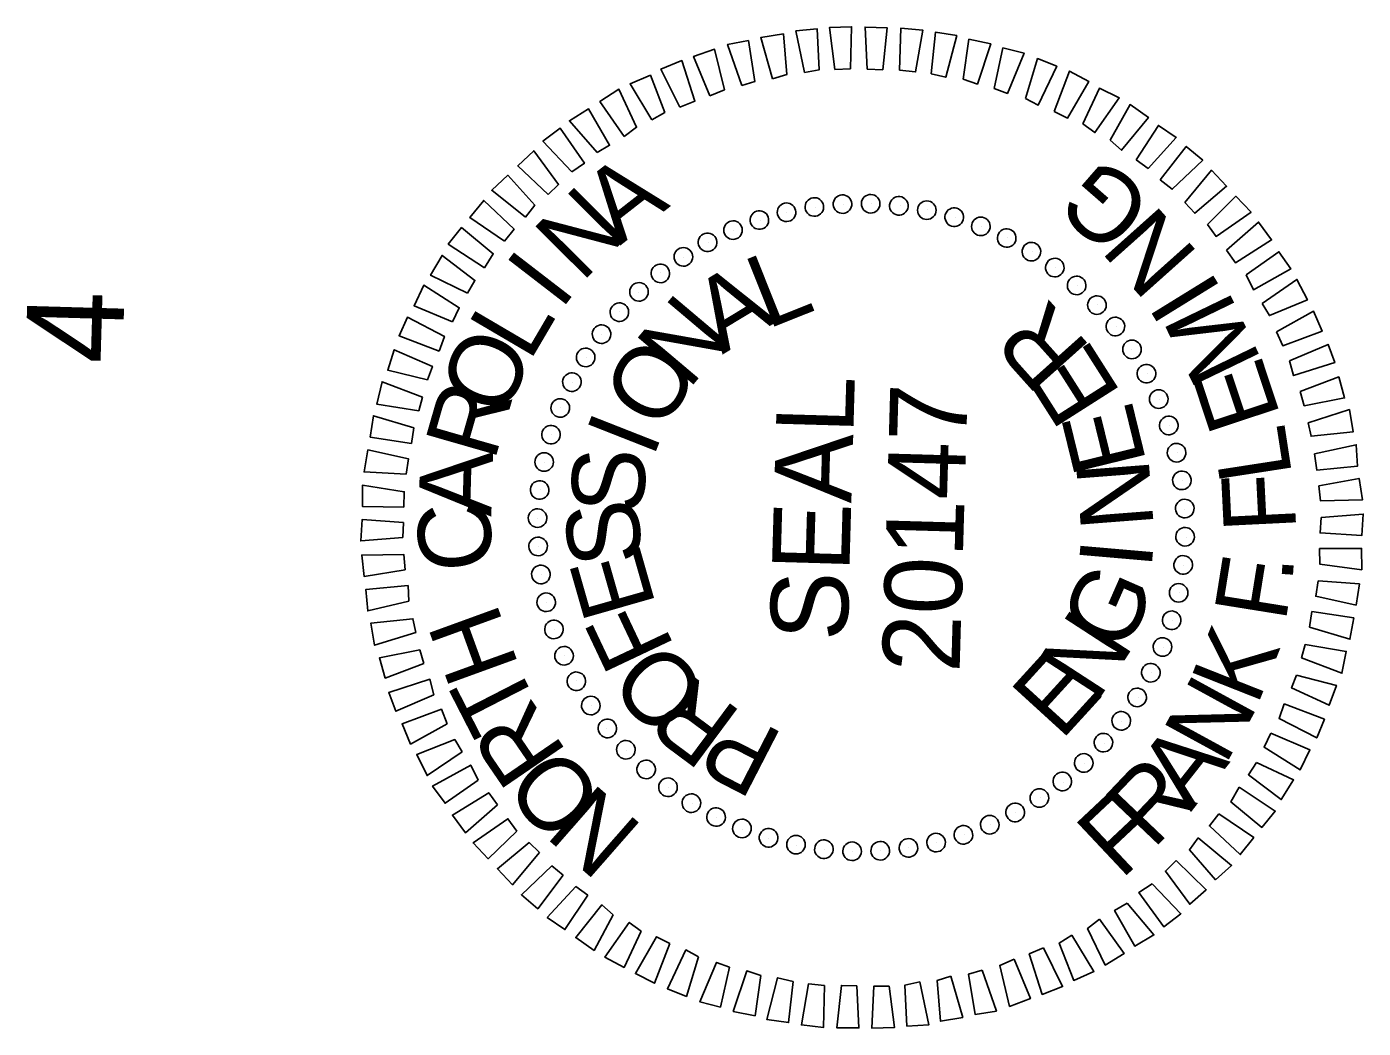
# Model space of a CAD drawing. Extents: x 2098230 to 2099272, y 990384 to 991889.
# Drawn here: x 2098261.7 to 2098365.1, y 991811.7 to 991889.2 of the extents above; entities that cross this region are included whole.
import ezdxf

# ---------------------------------------------------------------- set-up
doc = ezdxf.new("R2010")
doc.units = 0
doc.layers.add('Sheet Data Field CELL', color=7, linetype='Continuous')
doc.layers.add('Sheet PE Seal Cell', color=7, linetype='Continuous')

msp = doc.modelspace()

# ---------------------------------------------------------------- linework, layer by layer
at = {"layer": 'Sheet PE Seal Cell'}
for p, q in [((2098327.07, 991875.54), (2098327.07, 991875.54)), ((2098320.49, 991874.83), (2098320.49, 991874.83)), ((2098322.71, 991875.22), (2098322.71, 991875.22)), ((2098324.86, 991875.46), (2098324.86, 991875.46)), ((2098329.26, 991875.38), (2098329.26, 991875.38)), ((2098331.35, 991875.02), (2098331.35, 991875.02)), ((2098316.4, 991873.45), (2098316.4, 991873.45)), ((2098318.43, 991874.24), (2098318.43, 991874.24)), ((2098333.54, 991874.46), (2098333.54, 991874.46)), ((2098335.57, 991873.75), (2098335.57, 991873.75)), ((2098314.42, 991872.51), (2098314.42, 991872.51)), ((2098337.55, 991872.89), (2098337.55, 991872.89)), ((2098339.47, 991871.83), (2098339.47, 991871.83)), ((2098312.54, 991871.36), (2098312.54, 991871.36)), ((2098341.28, 991870.58), (2098341.28, 991870.58)), ((2098310.76, 991870.16), (2098310.76, 991870.16)), ((2098309.06, 991868.66), (2098309.06, 991868.66)), ((2098342.99, 991869.18), (2098342.99, 991869.18)), ((2098344.55, 991867.69), (2098344.55, 991867.69)), ((2098307.57, 991867.15), (2098307.57, 991867.15)), ((2098306.17, 991865.39), (2098306.17, 991865.39)), ((2098346, 991865.99), (2098346, 991865.99)), ((2098347.2, 991864.21), (2098347.2, 991864.21)), ((2098304.97, 991863.62), (2098304.97, 991863.62)), ((2098348.4, 991862.37), (2098348.4, 991862.37)), ((2098303.91, 991861.7), (2098303.91, 991861.7)), ((2098349.34, 991860.34), (2098349.34, 991860.34)), ((2098303, 991859.73), (2098303, 991859.73)), ((2098350.13, 991858.32), (2098350.13, 991858.32)), ((2098302.29, 991857.65), (2098302.29, 991857.65)), ((2098350.72, 991856.25), (2098350.72, 991856.25)), ((2098301.78, 991855.51), (2098301.78, 991855.51)), ((2098351.11, 991854.09), (2098351.11, 991854.09)), ((2098301.42, 991853.37), (2098301.42, 991853.37)), ((2098351.3, 991851.88), (2098351.3, 991851.88)), ((2098301.21, 991851.18), (2098301.21, 991851.18)), ((2098351.38, 991849.68), (2098351.38, 991849.68)), ((2098301.29, 991848.97), (2098301.29, 991848.97)), ((2098301.53, 991846.82), (2098301.53, 991846.82)), ((2098351.22, 991847.54), (2098351.22, 991847.54)), ((2098301.92, 991844.65), (2098301.92, 991844.65)), ((2098350.86, 991845.39), (2098350.86, 991845.39)), ((2098302.51, 991842.54), (2098302.51, 991842.54)), ((2098350.35, 991843.26), (2098350.35, 991843.26)), ((2098303.3, 991840.56), (2098303.3, 991840.56)), ((2098349.64, 991841.18), (2098349.64, 991841.18)), ((2098304.24, 991838.58), (2098304.24, 991838.58)), ((2098348.73, 991839.2), (2098348.73, 991839.2)), ((2098347.67, 991837.28), (2098347.67, 991837.28)), ((2098305.39, 991836.7), (2098305.39, 991836.7)), ((2098346.42, 991835.47), (2098346.42, 991835.47)), ((2098306.59, 991834.87), (2098306.59, 991834.87)), ((2098308.09, 991833.22), (2098308.09, 991833.22)), ((2098345.07, 991833.76), (2098345.07, 991833.76)), ((2098343.53, 991832.2), (2098343.53, 991832.2)), ((2098309.6, 991831.68), (2098309.6, 991831.68)), ((2098311.36, 991830.33), (2098311.36, 991830.33)), ((2098341.88, 991830.75), (2098341.88, 991830.75)), ((2098313.17, 991829.07), (2098313.17, 991829.07)), ((2098340.1, 991829.55), (2098340.1, 991829.55)), ((2098315.09, 991828.02), (2098315.09, 991828.02)), ((2098338.21, 991828.4), (2098338.21, 991828.4)), ((2098317.07, 991827.11), (2098317.07, 991827.11)), ((2098336.24, 991827.46), (2098336.24, 991827.46)), ((2098319.1, 991826.4), (2098319.1, 991826.4)), ((2098321.24, 991825.89), (2098321.24, 991825.89)), ((2098332.1, 991826.08), (2098332.1, 991826.08)), ((2098334.21, 991826.67), (2098334.21, 991826.67)), ((2098323.38, 991825.53), (2098323.38, 991825.53)), ((2098325.57, 991825.36), (2098325.57, 991825.36)), ((2098327.78, 991825.45), (2098327.78, 991825.45)), ((2098329.93, 991825.69), (2098329.93, 991825.69))]:
    msp.add_line(p, q, dxfattribs=at)
for points in [[(2098321.86, 991885.65), (2098321.2, 991888.87), (2098322.85, 991889.02), (2098323.01, 991885.86)], [(2098324.21, 991885.88), (2098323.81, 991889.14), (2098325.51, 991889.19), (2098325.42, 991885.94)], [(2098326.72, 991885.91), (2098326.56, 991889.16), (2098328.26, 991889.11), (2098327.92, 991885.87)], [(2098329.22, 991885.83), (2098329.31, 991889.08), (2098331.01, 991888.93), (2098330.46, 991885.7)], [(2098317.03, 991884.64), (2098315.92, 991887.82), (2098317.53, 991888.12), (2098318.04, 991884.96)], [(2098319.39, 991885.17), (2098318.48, 991888.35), (2098320.24, 991888.64), (2098320.5, 991885.49)], [(2098331.66, 991885.56), (2098332, 991888.76), (2098333.64, 991888.51), (2098332.8, 991885.28)], [(2098334.15, 991885.14), (2098334.59, 991888.23), (2098336.28, 991887.88), (2098335.24, 991884.76)], [(2098314.55, 991883.86), (2098313.29, 991886.89), (2098314.91, 991887.45), (2098315.67, 991884.32)], [(2098336.53, 991884.42), (2098337.22, 991887.56), (2098338.86, 991887.16), (2098337.57, 991884.04)], [(2098312.23, 991882.97), (2098310.76, 991885.92), (2098312.38, 991886.57), (2098313.39, 991883.44)], [(2098338.96, 991883.65), (2098339.9, 991886.73), (2098341.38, 991886.13), (2098339.94, 991883.12)], [(2098310.05, 991881.99), (2098308.38, 991884.78), (2098309.95, 991885.44), (2098311.06, 991882.56)], [(2098341.18, 991882.64), (2098342.37, 991885.76), (2098343.85, 991884.96), (2098342.21, 991882.11)], [(2098307.91, 991880.7), (2098306.04, 991883.4), (2098307.51, 991884.36), (2098308.88, 991881.42)], [(2098343.4, 991881.67), (2098344.68, 991884.44), (2098346.21, 991883.69), (2098344.33, 991881)], [(2098305.82, 991879.46), (2098303.69, 991881.92), (2098305.17, 991882.83), (2098306.79, 991880.03)], [(2098345.52, 991880.41), (2098347.05, 991883.17), (2098348.47, 991882.18), (2098346.39, 991879.64)], [(2098303.88, 991877.96), (2098301.64, 991880.33), (2098302.97, 991881.34), (2098304.85, 991878.63)], [(2098347.52, 991878.9), (2098349.25, 991881.56), (2098350.62, 991880.62), (2098348.45, 991878.23)], [(2098349.38, 991877.35), (2098351.4, 991879.94), (2098352.67, 991878.86), (2098350.31, 991876.62)], [(2098302.03, 991876.21), (2098299.69, 991878.43), (2098300.92, 991879.6), (2098302.85, 991876.99)], [(2098300.28, 991874.46), (2098297.68, 991876.54), (2098298.92, 991877.7), (2098301, 991875.39)], [(2098351.28, 991875.6), (2098353.35, 991878.09), (2098354.52, 991876.85), (2098352.06, 991874.77)], [(2098298.67, 991872.61), (2098295.97, 991874.44), (2098297.06, 991875.76), (2098299.4, 991873.54)], [(2098353.03, 991873.89), (2098355.24, 991876.08), (2098356.41, 991874.85), (2098353.7, 991872.97)], [(2098297.11, 991870.55), (2098294.31, 991872.38), (2098295.35, 991873.66), (2098297.79, 991871.63)], [(2098354.52, 991871.9), (2098356.99, 991874.08), (2098358, 991872.7), (2098355.2, 991870.93)], [(2098295.8, 991868.59), (2098292.94, 991869.97), (2098293.84, 991871.5), (2098296.38, 991869.57)], [(2098356.02, 991870.01), (2098358.57, 991871.78), (2098359.48, 991870.46), (2098356.59, 991868.84)], [(2098357.26, 991867.77), (2098359.96, 991869.64), (2098360.77, 991868.07), (2098357.83, 991866.85)], [(2098294.64, 991866.37), (2098291.67, 991867.61), (2098292.42, 991869.19), (2098295.17, 991867.46)], [(2098293.62, 991864.1), (2098290.51, 991865.29), (2098291.15, 991866.72), (2098294.01, 991865.24)], [(2098358.39, 991865.59), (2098361.24, 991867.2), (2098361.9, 991865.64), (2098358.86, 991864.52)], [(2098292.71, 991861.88), (2098289.63, 991862.62), (2098290.13, 991864.2), (2098293.09, 991862.92)], [(2098359.38, 991863.36), (2098362.37, 991864.62), (2098362.88, 991863.21), (2098359.7, 991862.2)], [(2098360.21, 991860.98), (2098363.2, 991862.1), (2098363.65, 991860.48), (2098360.53, 991859.87)], [(2098292.04, 991859.49), (2098288.8, 991859.99), (2098289.2, 991861.73), (2098292.32, 991860.54)], [(2098291.47, 991856.96), (2098288.28, 991857.45), (2098288.53, 991859.1), (2098291.65, 991858.16)], [(2098360.84, 991858.56), (2098364.02, 991859.57), (2098364.32, 991857.86), (2098361.06, 991857.51)], [(2098291.05, 991854.57), (2098287.8, 991854.76), (2098288.1, 991856.46), (2098291.23, 991855.77)], [(2098361.32, 991856.15), (2098364.55, 991856.86), (2098364.65, 991855.2), (2098361.49, 991854.89)], [(2098361.65, 991853.69), (2098364.77, 991854.25), (2098365.02, 991852.59), (2098361.77, 991852.53)], [(2098290.88, 991852.03), (2098287.68, 991852.07), (2098287.67, 991853.72), (2098290.91, 991853.22)], [(2098290.81, 991849.68), (2098287.55, 991849.42), (2098287.65, 991851.07), (2098290.84, 991850.83)], [(2098361.83, 991851.23), (2098365.09, 991851.49), (2098364.99, 991849.84), (2098361.75, 991850.03)], [(2098361.71, 991848.83), (2098364.96, 991848.84), (2098364.97, 991847.19), (2098361.73, 991847.63)], [(2098290.99, 991847.17), (2098287.82, 991846.66), (2098287.62, 991848.32), (2098290.87, 991848.37)], [(2098291.27, 991844.76), (2098288.09, 991844), (2098287.94, 991845.66), (2098291.2, 991845.96)], [(2098361.59, 991846.34), (2098364.79, 991846.09), (2098364.54, 991844.45), (2098361.41, 991845.14)], [(2098361.12, 991843.95), (2098364.36, 991843.46), (2098364.06, 991841.81), (2098360.94, 991842.75)], [(2098291.8, 991842.34), (2098288.62, 991841.34), (2098288.32, 991843.05), (2098291.58, 991843.4)], [(2098360.6, 991841.41), (2098363.78, 991840.87), (2098363.44, 991839.18), (2098360.32, 991840.37)], [(2098292.43, 991839.93), (2098289.44, 991838.81), (2098288.99, 991840.37), (2098292.11, 991840.99)], [(2098293.21, 991837.5), (2098290.27, 991836.24), (2098289.71, 991837.7), (2098292.89, 991838.71)], [(2098359.93, 991839.03), (2098363.01, 991838.24), (2098362.46, 991836.71), (2098359.55, 991838.04)], [(2098294.24, 991835.27), (2098291.4, 991833.7), (2098290.74, 991835.27), (2098293.78, 991836.39)], [(2098358.97, 991836.81), (2098362.08, 991835.62), (2098361.49, 991834.18), (2098358.58, 991835.67)], [(2098357.95, 991834.54), (2098360.96, 991833.25), (2098360.22, 991831.72), (2098357.42, 991833.45)], [(2098295.38, 991833.09), (2098292.68, 991831.26), (2098291.87, 991832.89), (2098294.81, 991834.05)], [(2098356.83, 991832.27), (2098359.7, 991830.93), (2098358.75, 991829.41), (2098356.21, 991831.33)], [(2098296.62, 991830.9), (2098294.07, 991829.12), (2098293.1, 991830.45), (2098296.05, 991832.07)], [(2098355.48, 991830.36), (2098358.28, 991828.52), (2098357.24, 991827.25), (2098354.85, 991829.22)], [(2098298.12, 991829.01), (2098295.65, 991826.83), (2098294.64, 991828.21), (2098297.44, 991829.93)], [(2098353.92, 991828.3), (2098356.62, 991826.47), (2098355.58, 991825.15), (2098353.19, 991827.37)], [(2098299.61, 991826.96), (2098297.39, 991824.83), (2098296.23, 991826.06), (2098298.93, 991827.93)], [(2098301.36, 991825.31), (2098299.29, 991822.82), (2098298.12, 991824.05), (2098300.58, 991826.08)], [(2098352.31, 991826.45), (2098354.9, 991824.32), (2098353.67, 991823.2), (2098351.64, 991825.51)], [(2098303.21, 991823.56), (2098301.24, 991820.96), (2098299.97, 991822.05), (2098302.33, 991824.28)], [(2098350.61, 991824.69), (2098352.95, 991822.43), (2098351.67, 991821.31), (2098349.79, 991823.87)], [(2098348.76, 991822.9), (2098350.99, 991820.58), (2098349.66, 991819.57), (2098347.74, 991822.22)], [(2098305.12, 991822), (2098303.34, 991819.35), (2098301.97, 991820.29), (2098304.19, 991822.68)], [(2098307.07, 991820.5), (2098305.59, 991817.74), (2098304.17, 991818.73), (2098306.2, 991821.27)], [(2098346.82, 991821.4), (2098348.9, 991818.94), (2098347.42, 991818.08), (2098345.85, 991820.83)], [(2098309.24, 991819.23), (2098307.91, 991816.42), (2098306.43, 991817.21), (2098308.31, 991819.91)], [(2098344.68, 991820.16), (2098346.6, 991817.51), (2098345.13, 991816.6), (2098343.76, 991819.44)], [(2098311.46, 991818.27), (2098310.27, 991815.2), (2098308.79, 991815.94), (2098310.43, 991818.8)], [(2098342.54, 991818.92), (2098344.26, 991816.12), (2098342.69, 991815.42), (2098341.58, 991818.3)], [(2098313.68, 991817.25), (2098312.74, 991814.18), (2098311.26, 991814.77), (2098312.7, 991817.78)], [(2098340.36, 991817.94), (2098341.83, 991814.94), (2098340.26, 991814.34), (2098339.25, 991817.47)], [(2098316.06, 991816.44), (2098315.37, 991813.35), (2098313.78, 991813.75), (2098315.07, 991816.81)], [(2098338.09, 991817.05), (2098339.35, 991814.01), (2098337.73, 991813.41), (2098336.97, 991816.58)], [(2098318.49, 991815.81), (2098318.05, 991812.68), (2098316.36, 991813.02), (2098317.4, 991816.15)], [(2098320.98, 991815.34), (2098320.64, 991812.15), (2098318.95, 991812.4), (2098319.79, 991815.63)], [(2098333.2, 991815.74), (2098334.11, 991812.56), (2098332.4, 991812.26), (2098332.14, 991815.42)], [(2098335.61, 991816.22), (2098336.72, 991813.04), (2098335.06, 991812.79), (2098334.55, 991815.9)], [(2098323.42, 991815.02), (2098323.33, 991811.77), (2098321.63, 991811.97), (2098322.18, 991815.16)], [(2098325.92, 991815), (2098326.08, 991811.74), (2098324.38, 991811.74), (2098324.72, 991815.03)], [(2098328.42, 991814.98), (2098328.83, 991811.77), (2098327.08, 991811.72), (2098327.22, 991814.96)], [(2098330.78, 991815.31), (2098331.49, 991811.99), (2098329.79, 991811.89), (2098329.63, 991815.04)]]:
    msp.add_lwpolyline(points, close=True, dxfattribs=at)
for centre, major_axis in [((2098320.48, 991874.84), (-0.166, 0.7)), ((2098322.63, 991875.25), (-0.104, 0.712)), ((2098324.81, 991875.47), (-0.042, 0.718)), ((2098326.99, 991875.5), (0.021, 0.719)), ((2098329.17, 991875.34), (0.083, 0.714)), ((2098331.33, 991875), (0.145, 0.704)), ((2098318.38, 991874.24), (-0.226, 0.683)), ((2098333.45, 991874.46), (0.206, 0.689)), ((2098335.51, 991873.75), (0.265, 0.669)), ((2098316.34, 991873.46), (-0.285, 0.66)), ((2098337.51, 991872.85), (0.323, 0.643)), ((2098314.37, 991872.51), (-0.342, 0.633)), ((2098339.42, 991871.79), (0.377, 0.612)), ((2098312.5, 991871.39), (-0.395, 0.601)), ((2098341.23, 991870.56), (0.429, 0.577)), ((2098310.72, 991870.11), (-0.446, 0.564)), ((2098309.07, 991868.68), (-0.494, 0.523)), ((2098342.92, 991869.18), (0.478, 0.537)), ((2098344.49, 991867.66), (0.523, 0.494)), ((2098307.55, 991867.11), (-0.537, 0.478)), ((2098306.17, 991865.41), (-0.577, 0.429)), ((2098345.92, 991866), (0.564, 0.446)), ((2098304.94, 991863.61), (-0.612, 0.377)), ((2098347.2, 991864.23), (0.601, 0.395)), ((2098348.32, 991862.36), (0.633, 0.342)), ((2098303.88, 991861.7), (-0.643, 0.323)), ((2098349.27, 991860.39), (0.66, 0.285)), ((2098302.98, 991859.7), (-0.669, 0.265)), ((2098350.05, 991858.35), (0.683, 0.226)), ((2098302.26, 991857.64), (-0.689, 0.206)), ((2098350.65, 991856.24), (0.7, 0.166)), ((2098301.73, 991855.52), (-0.704, 0.145)), ((2098351.06, 991854.1), (0.712, 0.104)), ((2098301.38, 991853.36), (-0.714, 0.083)), ((2098301.22, 991851.18), (-0.719, 0.021)), ((2098351.28, 991851.92), (0.718, 0.042)), ((2098301.26, 991848.99), (-0.718, -0.042)), ((2098351.31, 991849.74), (0.719, -0.021)), ((2098351.16, 991847.56), (0.714, -0.083)), ((2098301.48, 991846.82), (-0.712, -0.104)), ((2098350.81, 991845.4), (0.704, -0.145)), ((2098301.89, 991844.67), (-0.7, -0.166)), ((2098350.27, 991843.28), (0.689, -0.206)), ((2098302.49, 991842.57), (-0.683, -0.226)), ((2098349.56, 991841.21), (0.669, -0.265)), ((2098303.27, 991840.53), (-0.66, -0.285)), ((2098304.22, 991838.56), (-0.633, -0.342)), ((2098348.66, 991839.22), (0.643, -0.323)), ((2098305.34, 991836.68), (-0.601, -0.395)), ((2098347.6, 991837.31), (0.612, -0.377)), ((2098346.37, 991835.5), (0.577, -0.429)), ((2098306.62, 991834.91), (-0.564, -0.446)), ((2098344.99, 991833.81), (0.537, -0.478)), ((2098308.05, 991833.26), (-0.523, -0.494)), ((2098309.62, 991831.74), (-0.478, -0.537)), ((2098343.47, 991832.24), (0.494, -0.523)), ((2098311.31, 991830.36), (-0.429, -0.577)), ((2098341.81, 991830.81), (0.446, -0.564)), ((2098340.04, 991829.53), (0.395, -0.601)), ((2098313.12, 991829.13), (-0.377, -0.612)), ((2098338.17, 991828.41), (0.342, -0.633)), ((2098315.03, 991828.06), (-0.323, -0.643)), ((2098317.03, 991827.17), (-0.265, -0.669)), ((2098336.2, 991827.46), (0.285, -0.66)), ((2098319.09, 991826.45), (-0.206, -0.689)), ((2098334.16, 991826.68), (0.226, -0.683)), ((2098321.21, 991825.92), (-0.145, -0.704)), ((2098323.37, 991825.57), (-0.083, -0.714)), ((2098325.55, 991825.41), (-0.021, -0.719)), ((2098327.73, 991825.45), (0.042, -0.718)), ((2098329.91, 991825.67), (0.104, -0.712)), ((2098332.05, 991826.08), (0.166, -0.7))]:
    msp.add_ellipse(centre, major_axis=major_axis, ratio=0.999708, dxfattribs=at)

# ---------------------------------------------------------------- texts
at = {"layer": 'Sheet Data Field CELL'}
msp.add_text('4', height=7.5, rotation=88.3496, dxfattribs=at).set_placement((2098269.11, 991863.07))
at = {"layer": 'Sheet PE Seal Cell'}
for s, height, rotation, p in [('A', 5.63, 37.9667, (2098307.6, 991872.25)), ('G', 5.6, 138.9471, (2098349.12, 991875.56)), ('N', 5.63, 45.1685, (2098304.62, 991869.34)), ('N', 5.6, 131.7695, (2098352.47, 991871.56)), ('I', 5.63, 52.3697, (2098303, 991867.18)), ('L', 5.63, 21.7504, (2098318.97, 991865.77)), ('A', 5.63, 31.1098, (2098315.51, 991863.82)), ('I', 5.6, 121.686, (2098354.22, 991868.76)), ('N', 5.63, 49.8262, (2098312.88, 991861.05)), ('M', 5.6, 115.8396, (2098357.28, 991863.35)), ('R', 5.63, 131.831, (2098344.14, 991864.3)), ('L', 5.63, 59.5704, (2098300.59, 991863.2)), ('O', 5.63, 66.7707, (2098298.66, 991858.8)), ('O', 5.63, 59.183, (2098310.89, 991857.75)), ('E', 5.63, 122.4736, (2098346.44, 991860.78)), ('E', 5.6, 108.3412, (2098358.72, 991859.08)), ('R', 5.63, 73.9707, (2098297.87, 991855.48)), ('SEAL', 5.992, 88.3496, (2098325.18, 991841.63)), ('20147', 5.994, 88.3496, (2098333.86, 991839.19)), ('E', 5.63, 103.7613, (2098348.34, 991855.47)), ('I', 5.63, 68.5392, (2098310.13, 991855.72)), ('L', 5.6, 98.7591, (2098359.6, 991854.48)), ('A', 5.63, 88.3699, (2098297.64, 991851.28)), ('S', 5.63, 87.25, (2098309.4, 991851.44)), ('N', 5.63, 94.4059, (2098348.89, 991850.5)), ('F', 5.6, 92.8467, (2098359.91, 991850.24)), ('C', 5.63, 95.5694, (2098297.88, 991847.32)), ('S', 5.63, 96.6052, (2098309.4, 991847.84)), ('E', 5.63, 105.9606, (2098310.4, 991844.41)), ('I', 5.63, 85.0508, (2098348.7, 991847.16)), ('F', 5.6, 80.8685, (2098359.07, 991843.05)), ('G', 5.63, 66.3398, (2098346.71, 991840.61)), ('.', 5.6, 86.0929, (2098359.61, 991846.12)), ('H', 5.63, 109.969, (2098299.81, 991839.71)), ('F', 5.63, 115.3166, (2098311.86, 991841.17)), ('N', 5.63, 56.9835, (2098344.45, 991836.83)), ('K', 5.6, 68.4319, (2098356.88, 991836.58)), ('O', 5.63, 134.0308, (2098314.71, 991837.83)), ('E', 5.63, 47.6264, (2098341.71, 991833.9)), ('T', 5.63, 117.1693, (2098301.42, 991836.42)), ('R', 5.63, 143.3892, (2098317.16, 991836.06)), ('N', 5.6, 61.3315, (2098354.4, 991831.97)), ('R', 5.63, 124.3701, (2098303.57, 991833)), ('P', 5.63, 152.7484, (2098320.42, 991834.42)), ('A', 5.6, 51.7959, (2098351.75, 991828.42)), ('O', 5.63, 131.5713, (2098306.62, 991829.51)), ('R', 5.6, 46.3858, (2098348.82, 991825.48)), ('N', 5.63, 138.7731, (2098309.51, 991827.23)), ('F', 5.6, 43.227, (2098346.34, 991823.14))]:
    msp.add_text(s, height=height, rotation=rotation, dxfattribs=at).set_placement(p)

doc.saveas('drawing.dxf')
